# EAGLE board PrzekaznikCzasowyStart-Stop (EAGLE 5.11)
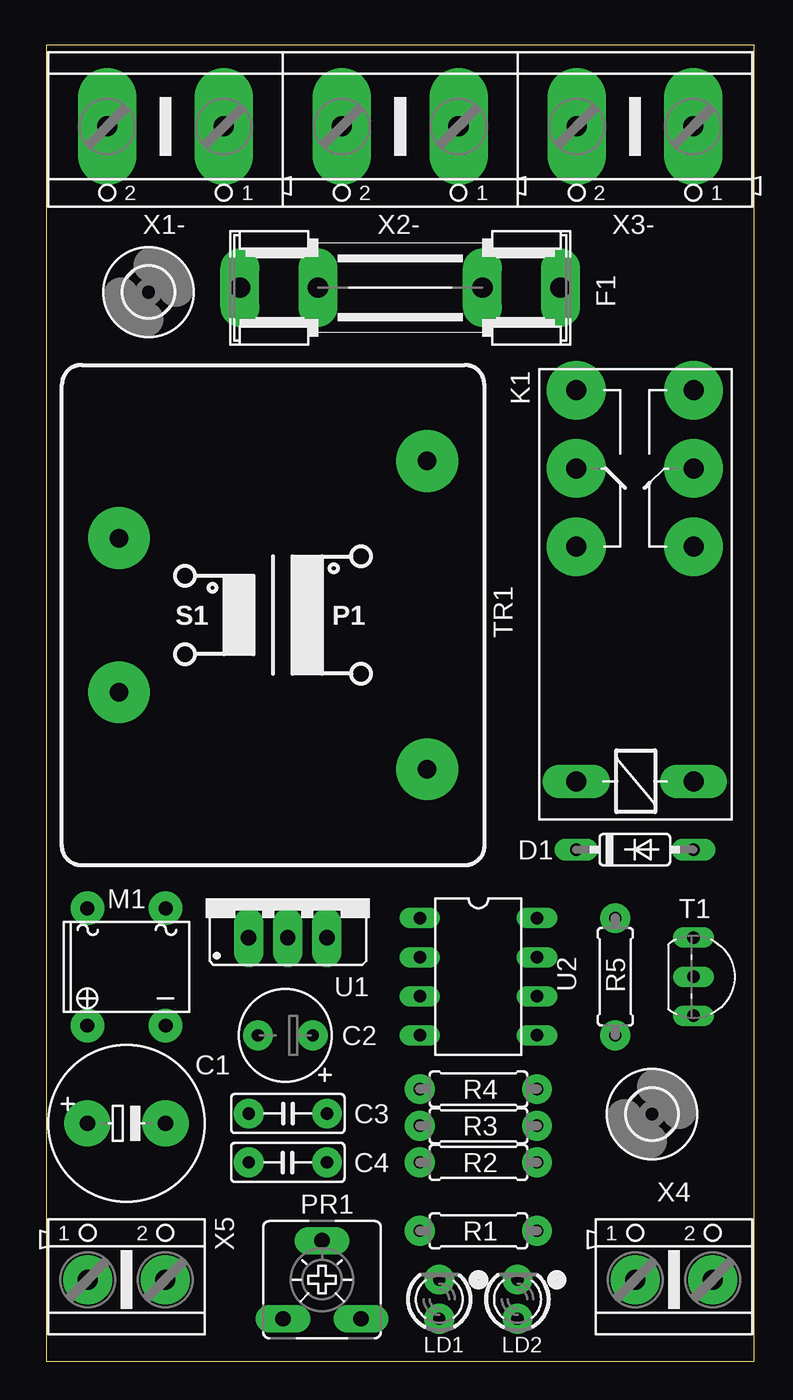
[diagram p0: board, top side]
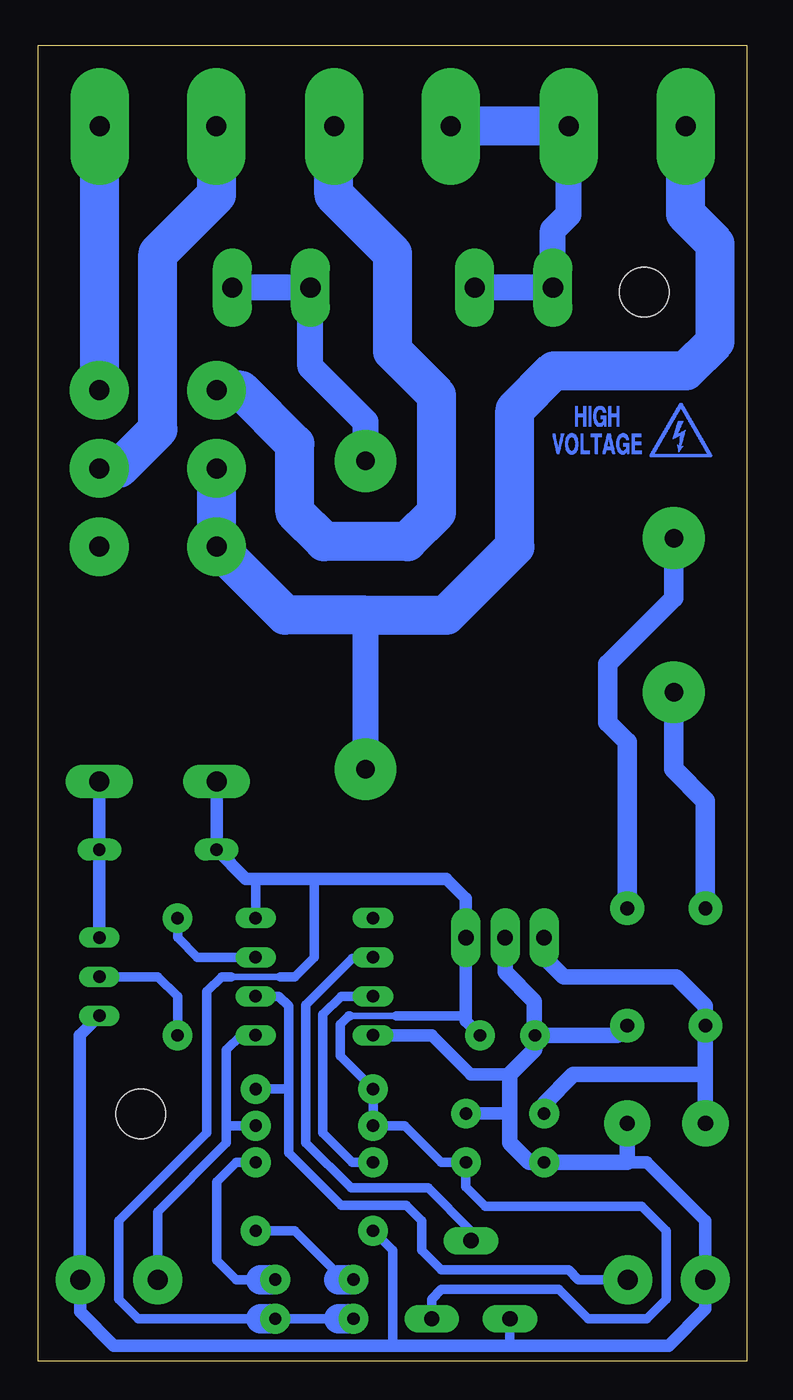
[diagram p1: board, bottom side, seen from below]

Size 46 x 85.5 mm. Coordinates in mm from the lower left corner, seen from the top.
Outline: 0,85.5 0,0 46,0 46,85.5 0,85.5
Copper layers (1*16): Top 0.035mm / dielectric 1.5mm / Bottom 0.035mm
Design rules "AVT": minimum track width 16mil, minimum drill 19mil, track to track 10mil, track to pad 10mil, pad to pad 10mil, via to via 10mil, smd to smd 10mil, copper to edge 20mil, drill to drill 10mil, minimum pad ring 10mil, minimum via ring 10mil, stop-mask expansion 4mil, vias tented up to drill 0mil, thermal gap 10mil

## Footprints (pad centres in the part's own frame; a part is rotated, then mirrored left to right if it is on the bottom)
E5-10,5 = drill 1 pad 3 round: + -2.54,0; - 2.54,0
E3,5-6 = drill 0.8 pad 1.93 round: + -1.778,0; - 1.778,0
C050-025X075 = drill 0.8 pad 1.93 round: 1 -2.54,0; 2 2.54,0
DO35-7 = drill 0.8 pad 1.422 long: A 3.81,0; C -3.81,0
SHK20L = drill 1.321 pad 2.54 long: 1A -10.414,0; 1B -5.334,0; 2A 10.414,0; 2B 5.334,0
3,2_SMALL = hole 3.2: 0,0
F4052 = drill 1.3 pad 2.184 long: 1 -3.81,3.81; 2 -3.81,-3.81 | drill 1.3 pad 3.81 round: O1 11.43,-3.81; O2 11.43,3.81; P1 16.51,-3.81; P2 16.51,3.81; S1 21.59,-3.81; S2 21.59,3.81
LED3MM = drill 0.8 pad 1.93 round: A -1.27,0; K 1.27,0
B-DIL = drill 0.9 pad 2.184 round: + -2.54,-3.81; - 2.54,-3.81; AC1 2.54,3.81; AC2 -2.54,3.81
CA6 = drill 1 pad 1.778 long: A -2.54,-2.54; E 2.54,-2.54; S 0,2.54
0207/7 = drill 0.8 pad 1.93 round: 1 -3.81,0; 2 3.81,0
TO92-EBC = drill 0.813 long: B 0,-1.27; C -2.54,-1.27; E 2.54,-1.27
EI30_AVT = drill 1.2 pad 4 round: 1 -10.008,10.008; 5 -10.008,-10.008; 7 10.008,-5.004; 9 10.008,5.004
78XXS = drill 1 pad 1.93 long: GND 0,-2.54; IN -2.54,-2.54; OUT 2.54,-2.54
DIL08 = drill 0.813 long: 1 -3.81,-3.81; 2 -1.27,-3.81; 3 1.27,-3.81; 4 3.81,-3.81; 5 3.81,3.81; 6 1.27,3.81; 7 -1.27,3.81; 8 -3.81,3.81
X2.2 = drill 1.3 pad 3.81 long: 1 -3.785,0; 2 3.785,0
AK500/2 = drill 1.3 pad 3.175 round: 1 -2.515,0; 2 2.515,0

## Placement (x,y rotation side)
C1  1000uF  [E5-10,5]  5.22,15.45 0 top
C2  100uF  [E3,5-6]  15.54,21.16 180 top
C3  100nF  [C050-025X075]  15.7,16.08 0 top
C4  100nF  [C050-025X075]  15.7,12.91 180 top
D1  1N4148  [DO35-7]  38.24,33.23 0 top
F1  100mA  [SHK20L]  23,69.74 0 top
H3  MOUNT-HOLE3,2_SMALL  [3,2_SMALL]  6.65,69.45 0 top
H5  MOUNT-HOLE3,2_SMALL  [3,2_SMALL]  39.35,16.05 0 top
K1  HF115F  [F4052]  38.24,41.48 90 top
LD1  G  [LED3MM]  25.54,4.02 90 top
LD2  R  [LED3MM]  30.62,4.02 90 top
M1  DF08  [B-DIL]  5.22,25.61 0 top
PR1  10k  [CA6]  17.92,5.29 0 top
R1  330  [0207/7]  28.08,8.46 0 top
R2  330  [0207/7]  28.08,12.91 0 top
R3  10k  [0207/7]  28.08,15.29 180 top
R4  4k7  [0207/7]  28.08,17.67 180 top
R5  4k7  [0207/7]  36.97,24.97 90 top
T1  BC547  [TO92-EBC]  43.32,24.97 270 top
TR1  6V/1.2VA  [EI30_AVT]  14.74,48.47 180 top
U1  7805  [78XXS]  15.7,30.05 0 top
U2  ATtiny13  [DIL08]  28.08,24.97 270 top
U$3  !HV  [HV]  2.05,58.62 0 top
X1-  [X2.2]  7.76,80.21 180 top
X2-  [X2.2]  23,80.21 180 top
X3-  [X2.2]  38.24,80.21 180 top
X4  STOP  [AK500/2]  40.78,5.29 0 top
X5  START  [AK500/2]  5.22,5.29 0 top

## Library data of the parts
C1-C4 R1-R5 = rcl
D1 = diode
F1 = fuse; OC_FARNELL: unknown; OC_NEWARK: unknown
H3 H5 = holes
K1 = relay; OC_FARNELL: unknown; OC_NEWARK: unknown
LD1 LD2 = led
M1 = rectifier
PR1 = pot
T1 = transistor-npn
TR1 = trafo
U1 = v-reg
U2 = atmel; MPN: ATTINY13-20PU; OC_FARNELL: 9171550; OC_NEWARK: 96K6521
U$3 = symbole
X1- X2- X3- = con-ptr750
X4 X5 = con-ptr500+

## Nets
+5V: C2.+ C4.1 D1.C K1.1 LD1.A LD2.A PR1.E R3.2 R4.2 U1.OUT U2.8
GND: C1.- C2.- C3.2 C4.2 M1.- PR1.A R1.1 T1.E U1.GND U2.4 X4.2 X5.1
N$1: PR1.S U2.2
N$2: LD2.K R2.2
N$3: F1.2A F1.2B TR1.5
N$4: LD1.K R1.2
N$5: F1.1A F1.1B X1-.1 X2-.2
N$6: K1.S2 X2-.1
N$7: R3.1 U2.5 X4.1
N$8: R2.1 U2.3
N$9: R4.1 U2.6 X5.2
N$10: M1.AC1 TR1.7
N$11: K1.P1 X3-.2
N$12: D1.A K1.2 T1.C
N$13: M1.AC2 TR1.9
N$14: K1.O2 K1.P2 TR1.1 X1-.2
N$15: K1.S1 X3-.1
N$16: C1.+ C3.1 M1.+ U1.IN
N$18: R5.1 T1.B
PK: R5.2 U2.7

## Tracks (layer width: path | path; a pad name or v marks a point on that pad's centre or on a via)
+5V
  Bottom 0.406: 25.78,22.43 22.76,22.43 | 30.3,24.97 33.48,24.97
  Bottom 0.61: 22.76,22.43 18.24,22.43 | 31.89,31.32 U2.8 | 31.57,2.74 39.51,2.74 40.78,4.02 40.78,9.1 35.06,14.81 35.06,24.02 34.11,24.97 33.48,24.97 | 28.08,31.32 28.08,26.24 29.35,24.97 30.3,24.97 | LD2.A 26.49,2.74 | 25.78,22.43 25.86,22.43 26.41,21.87 26.41,19.81 R4.2 R3.2 22.21,15.29 19.83,12.91 C4.1 18.24,11.32 16.97,10.05 6.81,10.05 5.22,8.46 5.22,4.02 6.49,2.74 10.3,2.74 12.2,4.65 19.83,4.65 20.46,4.02 PR1.E
  Bottom 0.813: K1.1 D1.C 32.53,31.32 31.89,31.32 28.08,31.32 19.51,31.32 18.24,30.05 U1.OUT 18.24,22.43 18.24,22.11 C2.+
  Bottom 1.93: 26.49,2.74 LD1.A | 31.57,2.74 LD2.A
GND
  Bottom 0.61: X4.2 43.32,4.04 | 23,1 23,7.19 R1.1 | 15.38,1 PR1.A
  Bottom 0.813: X4.2 43.3,3.2 41.1,1 23,1 15.38,1 5.06,1 2.68,3.38 2.68,5.26 X5.1 2.68,5.31 2.68,9.1 6.49,12.91 7.76,12.91 | 15.38,16.08 C3.2 | T1.E 43.32,21.16 43.32,4.04 | U2.4 20.46,21.16 17.92,18.62 15.38,18.62
  Bottom 1.016: C1.- 7.76,12.91 C4.2 14.11,12.91 15.38,14.18 15.38,16.08 15.38,18.62 13.76,20.24 C2.- | C2.- 8.4,21.16 M1.- | C2.- 13.79,21.16 13.79,23.38 15.7,25.29 U1.GND
N$1
  Bottom 0.61: U2.2 25.62,26.16 28.64,23.14 28.64,14.18 25.7,11.24 21.33,11.24 20.7,11.24 17.92,8.46 PR1.S
N$2
  Bottom 0.61: 31.57,5.29 33.16,5.29 34.43,6.56 34.43,11.63 33.16,12.91 R2.2
  Bottom 1.93: LD2.K 31.57,5.29
N$3
  Bottom 1.676: TR1.5 24.75,61.01 28.33,64.59 F1.2B F1.2A
N$4
  Bottom 0.61: 26.17,5.29 29.35,8.46 R1.2
  Bottom 1.93: LD1.K 26.17,5.29 26.49,5.29
N$5
  Bottom 1.676: X1-.1 11.57,80.19 11.57,74.5 12.59,73.48 F1.1A F1.1B
  Bottom 2.54: X1-.1 X2-.2
N$6
  Bottom 1.676: 26.81,80.19 X2-.1
  Bottom 2.54: K1.S2 32.84,63.07 29.35,59.58 29.35,55.13 27.45,53.23 22.05,53.23 20.14,55.13 20.14,62.75 23,65.61 23,71.96 26.81,75.77 26.81,80.19
N$7
  Bottom 0.61: X4.1 38.27,9.71 33.8,14.18 33.8,15.29 | 33.8,15.29 R3.1 | U2.5 32.84,21.16 33.8,20.21 33.8,15.29
N$8
  Bottom 0.61: R2.1 25.62,12.91 27.52,14.81 27.52,22.51 26.33,23.7 U2.3
N$9
  Bottom 0.61: U2.6 30.38,23.7 29.75,23.07 29.75,17.67 | 29.75,17.67 R4.1 | 29.75,17.67 29.75,13.54 26.33,10.13 22.13,10.13 21.09,9.1 21.09,7.19 19.83,5.92 11.57,5.92 10.94,5.29 X5.2
N$10
  Bottom 1.27: M1.AC1 7.76,40.21 9.03,41.48 9.03,45.29 4.74,49.58 TR1.7
N$11
  Bottom 2.54: K1.P1 40.78,57.99 38.24,60.53 38.24,71.96 34.43,75.77 34.43,80.19 X3-.2
N$12
  Bottom 0.813: K1.2 D1.A T1.C
N$13
  Bottom 1.27: M1.AC2 2.68,36.4 4.74,38.46 TR1.9
N$14
  Bottom 1.676: TR1.1 24.75,48.47
  Bottom 2.54: X1-.2 3.98,74.52 2.05,72.59 2.05,66.24 3.95,64.34 12.52,64.34 15.06,61.8 15.06,52.91 19.51,48.47 24.75,48.47 29.98,48.47 K1.O2 K1.P2
N$15
  Bottom 2.54: K1.S1 42.03,63.71 X3-.1
N$16
  Bottom 1.016: U1.IN 13.16,26.24 11.89,24.97 4.59,24.97 2.68,23.07 M1.+ 2.68,18.62 | 2.68,18.62 11.25,18.62 13.16,16.71 C3.1 | C1.+ 2.68,18.62
N$18
  Bottom 0.61: T1.B 38.24,24.97 36.97,23.7 R5.1
PK
  Bottom 0.61: U2.7 35.7,26.24 36.97,27.51 R5.2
